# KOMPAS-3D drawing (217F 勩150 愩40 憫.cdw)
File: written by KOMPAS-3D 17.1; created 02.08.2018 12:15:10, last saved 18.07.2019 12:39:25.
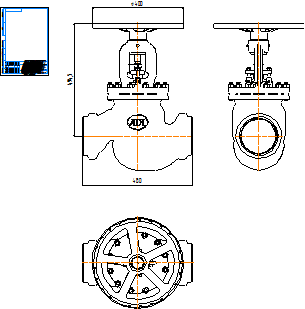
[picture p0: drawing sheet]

Sheet 1: A4, portrait

Title block, sheet 1: name: 217F Ду150 Ру40 СС; material: Внимание! Данный продукт является объектом авторского права ООО «Торговый Дом АДЛ». / Запрещается изменение, копирование, распространение / (в том числе путем копирования на другие сайты и ресурсы в Интернете) / или любое иное использование информации и объектов без предварительного / согласия правообладателя (ООО «Торговый Дом АДЛ»).; sheets: 1; organisation: ООО "Торговый дом АДЛ"; sheet format: A4; stored path: \\adlc.lan\data\АДЛ_ПКД\3D-модели\Поставщики\Zetkama\Вентили\217F\KOMPAS 2D\217F Ду150 Ру40 СС.cdw

Views: Вид 1, Проекционный вид 2, Проекционный вид 3
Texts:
  kka
  adl
Dimensions and other numbers on the sheet: 480; 494,5; 400; 1:1; 1; 217F Ду150 Ру40 СС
